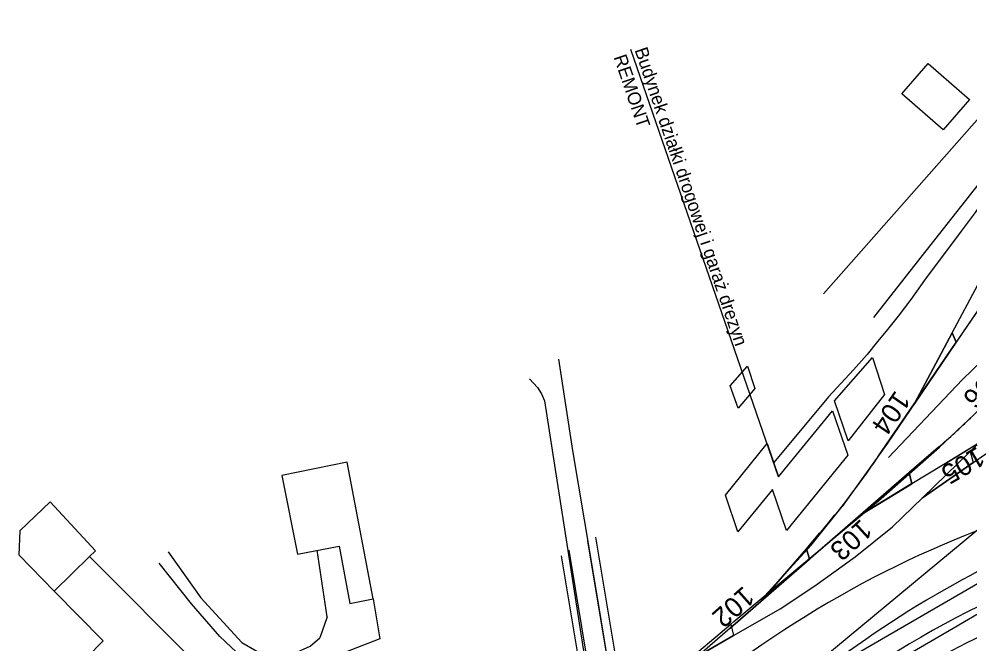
# Model space of a CAD drawing. Extents: x 6541740 to 6566395, y 5525066 to 5530361.
# Drawn here: x 6553767.4 to 6553839.7, y 5525345.4 to 5525392.9 of the extents above; entities that cross this region are included whole.
import ezdxf

# ---------------------------------------------------------------- set-up
doc = ezdxf.new("R2010")
doc.units = 0
for name, color, linetype in [('ps_wymiarowanie', 7, 'Continuous'), ('TOR_PRZEK_P-komponent', 7, 'Continuous'), ('TOR_PS_OPIS_O-opisy odwodnienia', 7, 'Continuous'), ('TOR_PS_OPIS_T-symbole geometrii', 7, 'Continuous'), ('TOR_PS_OPIS_T-ukresy', 7, 'Continuous'), ('TOR_PS_T-rowy otwarte nieumocnione', 7, 'Continuous'), ('TOR_PS_T-wypelnienia', 7, 'Continuous'), ('TOR_W-warstwa dodatkowa 2', 7, 'Continuous')]:
    doc.layers.add(name, color=color, linetype=linetype)

msp = doc.modelspace()

# ---------------------------------------------------------------- linework, layer by layer
at = {"layer": 'ps_wymiarowanie'}
for p, q in [((6553792.371, 5525359.253), (6553787.402, 5525358.257)), ((6553794.336, 5525348.887), (6553792.371, 5525359.253)), ((6553787.402, 5525358.257), (6553788.601, 5525352.278)), ((6553767.508, 5525354.074), (6553769.788, 5525356.256)), ((6553769.788, 5525356.256), (6553773.226, 5525352.529)), ((6553767.426, 5525352.197), (6553767.508, 5525354.074)), ((6553770.106, 5525349.47), (6553767.426, 5525352.197)), ((6553773.226, 5525352.529), (6553772.787, 5525352.087)), ((6553788.601, 5525352.278), (6553791.758, 5525352.888)), ((6553791.749, 5525352.89), (6553792.565, 5525348.532)), ((6553770.106, 5525349.47), (6553772.787, 5525352.087)), ((6553772.787, 5525352.087), (6553784.045, 5525340.8)), ((6553773.823, 5525345.687), (6553770.106, 5525349.47)), ((6553792.565, 5525348.532), (6553794.336, 5525348.887)), ((6553772.582, 5525344.412), (6553773.823, 5525345.687))]:
    msp.add_line(p, q, dxfattribs=at)
for points in [[(6553839.662, 5525386.828), (6553837.659, 5525384.525), (6553834.524, 5525387.251), (6553836.528, 5525389.554)], [(6553821.482, 5525365.066), (6553822.792, 5525366.556), (6553823.351, 5525364.848), (6553822.079, 5525363.365), (6553821.482, 5525365.066)]]:
    msp.add_lwpolyline(points, close=True, dxfattribs=at)
at = {"layer": 'TOR_PRZEK_P-komponent'}
for p, q in [((6553832.705, 5525359.654), (6553843.607, 5525375.626)), ((6553838.343, 5525369.08), (6553835.451, 5525363.678)), ((6553838.345, 5525369.077), (6553835.451, 5525363.678)), ((6553838.658, 5525368.376), (6553838.343, 5525369.08)), ((6553835.451, 5525363.678), (6553838.658, 5525368.376)), ((6553833.42, 5525360.702), (6553835.451, 5525363.678)), ((6553844.051, 5525362.953), (6553837.705, 5525359.096)), ((6553837.308, 5525360.394), (6553835.089, 5525358.468)), ((6553837.705, 5525359.096), (6553840.166, 5525360.592)), ((6553837.705, 5525359.096), (6553835.281, 5525357.623)), ((6553837.705, 5525359.096), (6553835.281, 5525357.623)), ((6553835.089, 5525358.468), (6553829.056, 5525353.231)), ((6553831.396, 5525355.262), (6553835.089, 5525358.468)), ((6553835.089, 5525358.468), (6553835.281, 5525357.623)), ((6553835.279, 5525357.631), (6553831.396, 5525355.262)), ((6553835.281, 5525357.623), (6553831.396, 5525355.262)), ((6553835.281, 5525357.623), (6553831.396, 5525355.262)), ((6553831.396, 5525355.262), (6553821.467, 5525346.644)), ((6553831.396, 5525355.262), (6553827.5, 5525351.881)), ((6553831.396, 5525355.262), (6553829.056, 5525353.231)), ((6553829.056, 5525353.231), (6553831.396, 5525355.262)), ((6553827.263, 5525352.686), (6553828.274, 5525353.86)), ((6553829.056, 5525353.231), (6553827.5, 5525351.881)), ((6553827.263, 5525352.686), (6553823.807, 5525348.674)), ((6553827.5, 5525351.881), (6553827.263, 5525352.686)), ((6553827.5, 5525351.881), (6553821.467, 5525346.644)), ((6553823.807, 5525348.674), (6553827.5, 5525351.881)), ((6553821.467, 5525346.644), (6553823.807, 5525348.674)), ((6553821.467, 5525346.644), (6553816.157, 5525342.034)), ((6553821.467, 5525346.644), (6553816.259, 5525342.123))]:
    msp.add_line(p, q, dxfattribs=at)
for points in [[(6553838.343, 5525369.08), (6553838.658, 5525368.376), (6553835.451, 5525363.678), (6553838.343, 5525369.08)], [(6553835.281, 5525357.623), (6553835.089, 5525358.468), (6553831.396, 5525355.262), (6553835.281, 5525357.623)], [(6553827.263, 5525352.686), (6553827.5, 5525351.881), (6553823.807, 5525348.674), (6553827.263, 5525352.686)]]:
    msp.add_lwpolyline(points, dxfattribs=at)
for centre, major_axis, start_param, end_param in [((6553802.297, 5525495.36), (-7.962, 146.801), 3.519116, 3.556315), ((6553797.356, 5525447.541), (5.839, -107.654), 0.48818, 0.588545), ((6553873.525, 5525113.688), (-13.27, 244.668), 0.155336, 0.387968), ((6553881.677, 5525114.282), (-13.27, 244.668), 0.155336, 0.336977), ((6553880.025, 5525110.746), (-13.27, 244.668), 0.155336, 0.394582), ((6553879.511, 5525108.157), (-13.27, 244.668), 0.155336, 0.311441), ((6553896.633, 5525010.483), (-18.577, 342.535), 0.155336, 0.363275)]:
    msp.add_ellipse(centre, major_axis=major_axis, ratio=0.510219, start_param=start_param, end_param=end_param, dxfattribs=at)
at = {"layer": 'TOR_PS_OPIS_T-symbole geometrii'}
for p, q in [((6553812.111, 5525344.595), (6553810.664, 5525353.277)), ((6553812.703, 5525344.91), (6553811.26, 5525353.571)), ((6553810.69, 5525343.839), (6553809.234, 5525352.571)), ((6553810.098, 5525343.524), (6553808.662, 5525352.137))]:
    msp.add_line(p, q, dxfattribs=at)
at = {"layer": 'TOR_PS_OPIS_T-ukresy'}
for points in [[(6553828.555, 5525372.043), (6553842.895, 5525388.295)], [(6553832.39, 5525370.256), (6553835.721, 5525374.473), (6553842.03, 5525382.493), (6553845.481, 5525387.397)], [(6553842.356, 5525381.716), (6553841.314, 5525380.059), (6553840.083, 5525378.233), (6553839.037, 5525376.81), (6553836.239, 5525373.092), (6553835.2, 5525371.635), (6553834.237, 5525370.355), (6553833.331, 5525369.215), (6553832.672, 5525368.424), (6553831.883, 5525367.455), (6553830.842, 5525366.281), (6553828.935, 5525364.234), (6553824.784, 5525359.231)], [(6553835.506, 5525363.759), (6553838.029, 5525368.458), (6553838.354, 5525369.084), (6553840.307, 5525372.733), (6553842.889, 5525378.767)], [(6553840.812, 5525371.535), (6553838.656, 5525368.379)]]:
    msp.add_lwpolyline(points, dxfattribs=at)
msp.add_lwpolyline([(6553835.506, 5525363.759), (6553838.656, 5525368.379), (6553838.354, 5525369.084)], close=True, dxfattribs=at)
at = {"layer": 'TOR_PS_T-rowy otwarte nieumocnione'}
for points in [[(6553821.526, 5525346.951), (6553821.758, 5525347.145), (6553827.832, 5525352.221), (6553832.753, 5525356.333), (6553837.382, 5525360.392), (6553840.026, 5525362.892), (6553857.463, 5525379.67), (6553869.425, 5525391.224), (6553881.111, 5525402.501), (6553889.241, 5525410.121)], [(6553833.52, 5525359.614), (6553839.128, 5525365.534), (6553881.914, 5525406.895)], [(6553836.098, 5525356.56), (6553840.906, 5525359.907), (6553843.174, 5525361.451), (6553845.345, 5525363.119), (6553847.824, 5525365.239), (6553851.928, 5525369.079), (6553855.975, 5525373.083), (6553857.642, 5525374.635), (6553859.916, 5525376.815), (6553863.533, 5525380.35), (6553870.613, 5525387.216), (6553882.179, 5525398.448)], [(6553799.416, 5525323.582), (6553815.426, 5525333.175), (6553819.817, 5525335.779), (6553821.788, 5525336.948), (6553822.906, 5525337.6), (6553832.052, 5525342.937), (6553835.934, 5525345.202), (6553838.425, 5525346.655), (6553842.644, 5525349.117), (6553844.316, 5525350.093), (6553850.458, 5525353.61), (6553854.45, 5525355.897), (6553862.272, 5525360.371), (6553871.388, 5525365.635), (6553878.747, 5525370.008), (6553885.782, 5525374.102), (6553895.467, 5525379.718), (6553899.595, 5525382.158)], [(6553821.526, 5525346.951), (6553821.758, 5525347.145), (6553827.832, 5525352.221), (6553832.753, 5525356.333), (6553837.382, 5525360.392), (6553840.026, 5525362.892), (6553851.413, 5525373.848)], [(6553838.656, 5525368.379), (6553833.421, 5525360.7), (6553829.991, 5525355.89)], [(6553799.025, 5525326.216), (6553805.326, 5525329.837), (6553819.935, 5525338.234), (6553823.838, 5525340.5), (6553827.741, 5525342.768), (6553843.937, 5525352.179), (6553861.035, 5525361.943)], [(6553830.982, 5525352.057), (6553833.818, 5525354.348), (6553836.098, 5525356.56), (6553840.633, 5525360.957)], [(6553824.113, 5525349.114), (6553827.621, 5525352.965), (6553827.828, 5525353.202), (6553829.991, 5525355.89)], [(6553823.838, 5525340.5), (6553827.562, 5525343.587), (6553842.066, 5525355.613)], [(6553821.74, 5525346.088), (6553821.769, 5525346.105), (6553825.284, 5525348.125), (6553827.92, 5525349.861), (6553830.982, 5525352.057)], [(6553814.108, 5525340.66), (6553817.808, 5525343.798), (6553821.526, 5525346.951)], [(6553817.808, 5525343.798), (6553821.74, 5525346.088)]]:
    msp.add_lwpolyline(points, dxfattribs=at)
for points in [[(6553836.057, 5525356.519), (6553839.72, 5525360.072), (6553839.938, 5525359.234)], [(6553817.808, 5525343.798), (6553821.526, 5525346.951), (6553821.722, 5525346.078)]]:
    msp.add_lwpolyline(points, close=True, dxfattribs=at)
at = {"layer": 'TOR_PS_T-wypelnienia'}
for p, q in [((6553809.507, 5525360.158), (6553808.462, 5525367.087)), ((6553806.214, 5525365.584), (6553806.822, 5525364.924)), ((6553806.822, 5525364.924), (6553807.137, 5525364.466)), ((6553807.137, 5525364.466), (6553807.359, 5525363.919)), ((6553807.359, 5525363.919), (6553808.127, 5525359.037)), ((6553810.401, 5525354.87), (6553809.507, 5525360.158)), ((6553808.127, 5525359.037), (6553810.509, 5525343.782)), ((6553811.524, 5525348.217), (6553810.401, 5525354.87)), ((6553790.836, 5525347.519), (6553790.082, 5525352.564)), ((6553794.336, 5525348.887), (6553794.849, 5525345.841)), ((6553812.066, 5525344.797), (6553811.524, 5525348.217)), ((6553790.836, 5525347.519), (6553790.286, 5525345.904)), ((6553794.849, 5525345.841), (6553790.536, 5525344.176))]:
    msp.add_line(p, q, dxfattribs=at)
msp.add_lwpolyline([(6553829.404, 5525363.93), (6553832.303, 5525367.223), (6553833.214, 5525364.402), (6553830.441, 5525360.886)], close=True, dxfattribs=at)
for points in [[(6553778.769, 5525352.44), (6553781.242, 5525348.962), (6553784.35, 5525345.549), (6553785.492, 5525344.891), (6553786.757, 5525344.542), (6553788.317, 5525344.721), (6553789.543, 5525345.268), (6553790.286, 5525345.904)], [(6553790.536, 5525344.176), (6553787.979, 5525343.558), (6553786.304, 5525343.538), (6553784.764, 5525344.059), (6553782.697, 5525346.007), (6553780.537, 5525348.492), (6553778.079, 5525351.581)], [(6553790.836, 5525347.519), (6553790.286, 5525345.904)]]:
    msp.add_lwpolyline(points, dxfattribs=at)
at = {"layer": 'TOR_W-warstwa dodatkowa 2'}
msp.add_line((6553825.159, 5525358.14), (6553813.936, 5525390.613), dxfattribs=at)
msp.add_lwpolyline([(6553822.06, 5525353.963), (6553821.109, 5525356.751), (6553824.283, 5525360.688), (6553825.159, 5525358.14), (6553829.264, 5525363.171), (6553830.429, 5525359.8), (6553825.748, 5525354.063), (6553824.695, 5525357.185), (6553822.06, 5525353.963)], dxfattribs=at)

# ---------------------------------------------------------------- texts
at = {"layer": 'TOR_PS_OPIS_O-opisy odwodnienia'}
for s, rotation, p in [('106', 224.20118, (6553841.464, 5525366.611)), ('104', 235.44811, (6553834.048, 5525364.787)), ('105', 210.33421, (6553840.254, 5525360.49)), ('103', 222.38323, (6553831.413, 5525355.009)), ('102', 221.61966, (6553822.488, 5525349.915))]:
    msp.add_text(s, height=1.5, rotation=rotation, dxfattribs=at).set_placement(p)
at = {"layer": 'TOR_W-warstwa dodatkowa 2'}
for s, p in [('Budynek działki drogowej i garaż drezyn', (6553814.198, 5525390.588)), ('REMONT', (6553812.604, 5525390.045))]:
    msp.add_text(s, height=1, rotation=288.7976, dxfattribs=at).set_placement(p)

doc.saveas('drawing.dxf')
